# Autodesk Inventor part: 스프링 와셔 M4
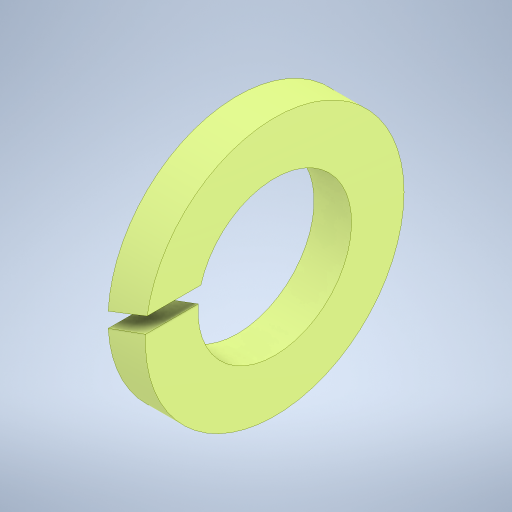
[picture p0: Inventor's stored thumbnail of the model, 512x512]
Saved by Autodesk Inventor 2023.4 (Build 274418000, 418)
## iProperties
Created: 2024-05
Part Number: 스프링 와셔 M4
Material: 강철, 연강
Description: 스프링 잠금 와셔
Document SubType Name: Modeling
Designer: EDU-001
Density: 7.85 g/cm^3
Appearance: 기본값
Author: jhkim
Sending System: Autodesk Inventor 2025
Preprocessor: ST-DEVELOPER v20
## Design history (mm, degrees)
node "스프링 와셔 M41"
node "솔리드1"
body "Solid1"
